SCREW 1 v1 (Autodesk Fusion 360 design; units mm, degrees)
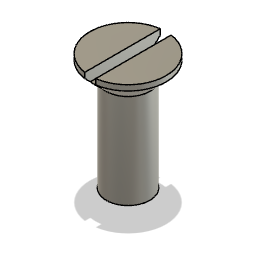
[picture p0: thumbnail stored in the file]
sketch "Sketch1" plane through (0, 0, 0) normal (0, 0, 1) x axis (1, 0, 0)
  line L1 (0, 118.8744) -> (0, 0)
  line L2 (99.9663, 0) -> (0, 0)
  line L3 (-5.25, 17.7321) -> (0, 17.7321)
  line L4 (-5.25, 16.9821) -> (-5.25, 17.7321)
  line L5 (-3, 14.7321) -> (-5.25, 16.9821)
  line L6 (-3, 1.7321) -> (-3, 14.7321)
  line L7 (0, 0) -> (-3, 1.7321)
  line L8 (0, 0) -> (0, 17.7321)
  point P1 (0, 0)
  point P2 (0, 0)
  point P4 (0, 0)
  point P6 (0, 17.7321)
  point P11 (0, 0)
  point P12 (0, 0)
  point P7 (-5.25, 17.7321)
  point P9 (-3, 14.7321)
  point P8 (-5.25, 16.9821)
  point P10 (-3, 1.7321)
  coincident P1 P2
  vertical L1
  coincident P1 P4
  perpendicular L1 L2
  coincident L1 P6
  perpendicular L1 L3
  perpendicular L3 L4
  perpendicular L3 L6
  coincident P1 P11
  coincident P1 P12
  dimension "d1" distance L1 L4 = 5.25
  dimension "d2" distance L1 L6 = 3
  dimension "d3" distance P7 P9 = 3
  dimension "d4" distance P7 P8 = 0.75
  dimension "d5" distance P9 P10 = 13
  dimension "d6" angle L1 L7 = 60
revolve "Revolve1" sketch "Sketch1" AlongAngle 360
sketch "Sketch2" plane through (0, 0, 0) normal (0, 0, 1) x axis (1, 0, 0)
  line L1 (0.75, 21.4072) -> (-0.75, 21.4072)
  line L2 (0.75, 16.2321) -> (0.75, 21.4072)
  line L3 (-0.75, 16.2321) -> (0.75, 16.2321)
  line L4 (-0.75, 21.4072) -> (-0.75, 16.2321)
  line L5 (-5.25, 17.7321) -> (5.25, 17.7321)
  point P2 (-0.75, 21.4072)
  point P3 (0.75, 21.4072)
  point P1 (0, 0)
  point P4 (0.75, 16.2321)
  horizontal L1
  vertical L2
  horizontal L3
  vertical L4
  dimension "d8" distance P2 P3 = 1.5
  dimension "d9" distance P1 L2 = 0.75
  dimension "d13" distance P4 L5 = 1.5
extrude "Extrude1" cut sketch "Sketch2" profile of L1 L2 L3 L4 distance 5.25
